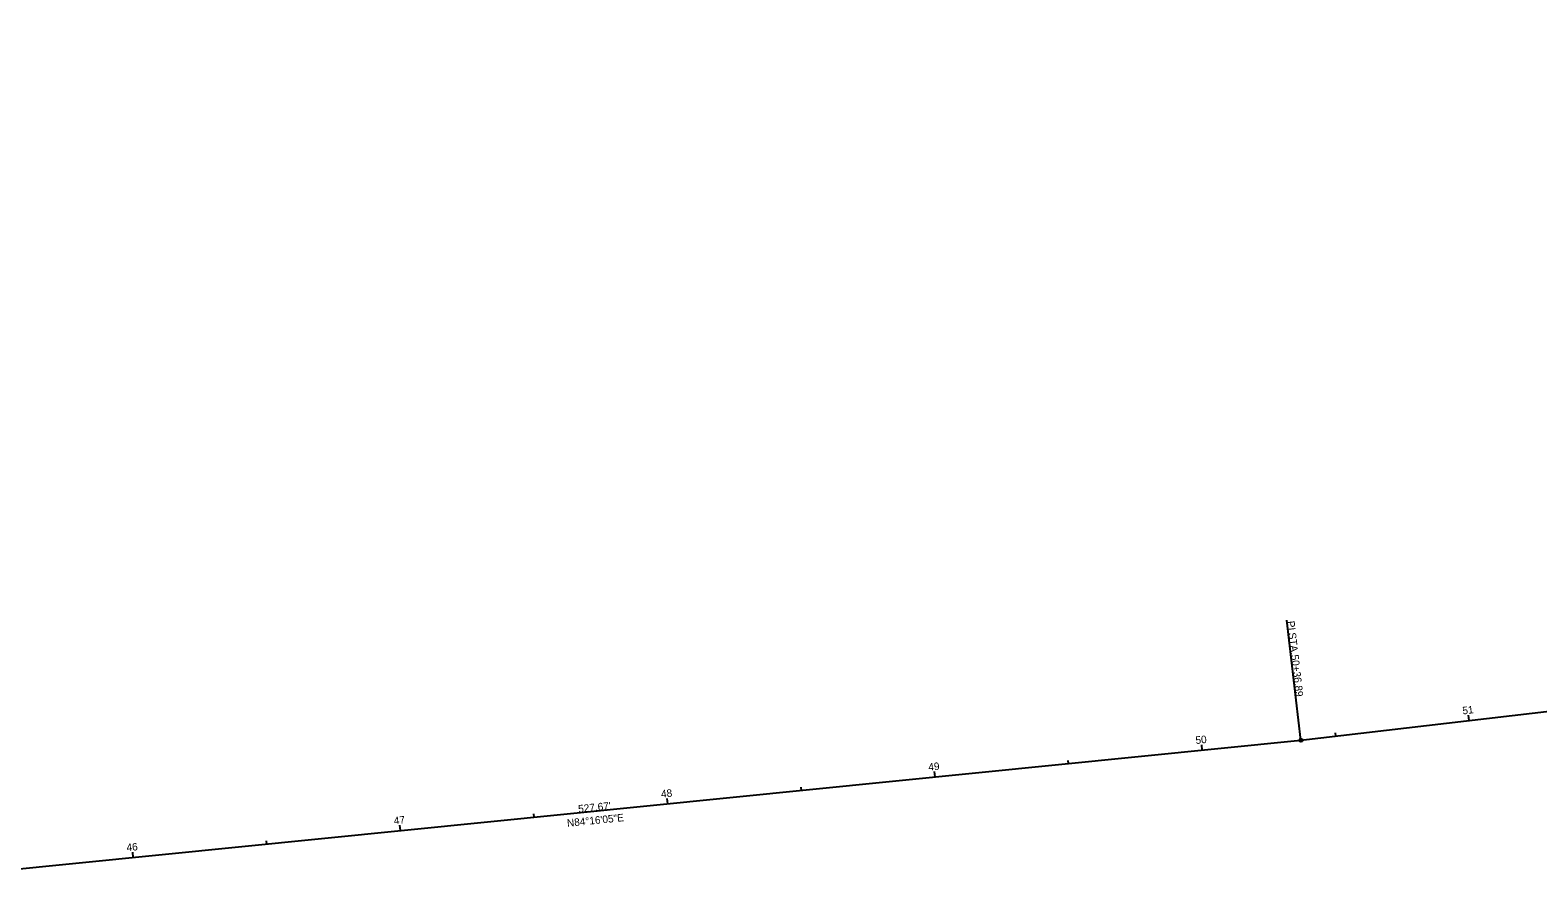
# Model space of a CAD drawing. Extents: x 198556 to 202876, y 391595 to 392065.
# Drawn here: x 200145 to 200707, y 391702 to 392019 of the extents above; entities that cross this region are included whole.
import ezdxf

# ---------------------------------------------------------------- set-up
doc = ezdxf.new("R2010")
doc.units = 0
for name, color, linetype in [('GE_X_Alignment', 7, 'Continuous'), ('GE_X_Alignment_100_Bearings', 7, 'Continuous'), ('GE_X_Alignment_100_Cardinal_Points', 7, 'Continuous'), ('GE_X_Alignment_100_Distances', 7, 'Continuous'), ('GE_X_Alignment_100_Stations', 7, 'Continuous')]:
    doc.layers.add(name, color=color, linetype=linetype)

msp = doc.modelspace()

# ---------------------------------------------------------------- linework, layer by layer
at = {"layer": 'GE_X_Alignment'}
for p, q in [((200618.31, 391754.7), (202874.43, 392018.93)), ((200093.28, 391702), (200618.31, 391754.7))]:
    msp.add_line(p, q, dxfattribs=at)
at = {"layer": 'GE_X_Alignment_100_Cardinal_Points'}
msp.add_line((200618.31, 391754.7), (200613.08, 391799.39), dxfattribs=at)
msp.add_circle((200618.31, 391754.7), 0.6, dxfattribs=at)
at = {"layer": 'GE_X_Alignment_100_Stations'}
for p, q in [((200680.99, 391762.04), (200680.76, 391764.02)), ((200581.6, 391751.01), (200581.4, 391753)), ((200631.33, 391756.22), (200631.19, 391757.41)), ((200531.85, 391746.02), (200531.73, 391747.21)), ((200482.1, 391741.02), (200481.9, 391743.01)), ((200432.35, 391736.03), (200432.23, 391737.22)), ((200382.6, 391731.04), (200382.4, 391733.03)), ((200332.85, 391726.04), (200332.73, 391727.24)), ((200283.1, 391721.05), (200282.9, 391723.04)), ((200183.6, 391711.06), (200183.4, 391713.05)), ((200233.35, 391716.06), (200233.23, 391717.25))]:
    msp.add_line(p, q, dxfattribs=at)

# ---------------------------------------------------------------- texts
at = {"layer": 'GE_X_Alignment_100_Bearings'}
msp.add_text('N84°16\'05"E', height=2.8, rotation=5.7319, dxfattribs=at).set_placement((200345.22, 391722.46))
at = {"layer": 'GE_X_Alignment_100_Cardinal_Points'}
for s, p in [('PI', (200613.17, 391798.93)), (' STA. ', (200613.55, 391795.64)), ('50+36.89', (200614.64, 391786.38))]:
    msp.add_text(s, height=2.8, rotation=276.68, dxfattribs=at).set_placement(p)
at = {"layer": 'GE_X_Alignment_100_Distances'}
msp.add_text("527.67'", height=2.8, rotation=5.7319, dxfattribs=at).set_placement((200349.39, 391727.74))
at = {"layer": 'GE_X_Alignment_100_Stations'}
for s, rotation, p in [('51', 6.68, (200678.61, 391764.28)), ('50', 5.7319, (200579.21, 391753.28)), ('49', 5.7319, (200479.76, 391743.3)), ('48', 5.7319, (200380.23, 391733.31)), ('47', 5.7319, (200280.74, 391723.32)), ('46', 5.7319, (200181.23, 391713.34))]:
    msp.add_text(s, height=2.8, rotation=rotation, dxfattribs=at).set_placement(p)

doc.saveas('drawing.dxf')
